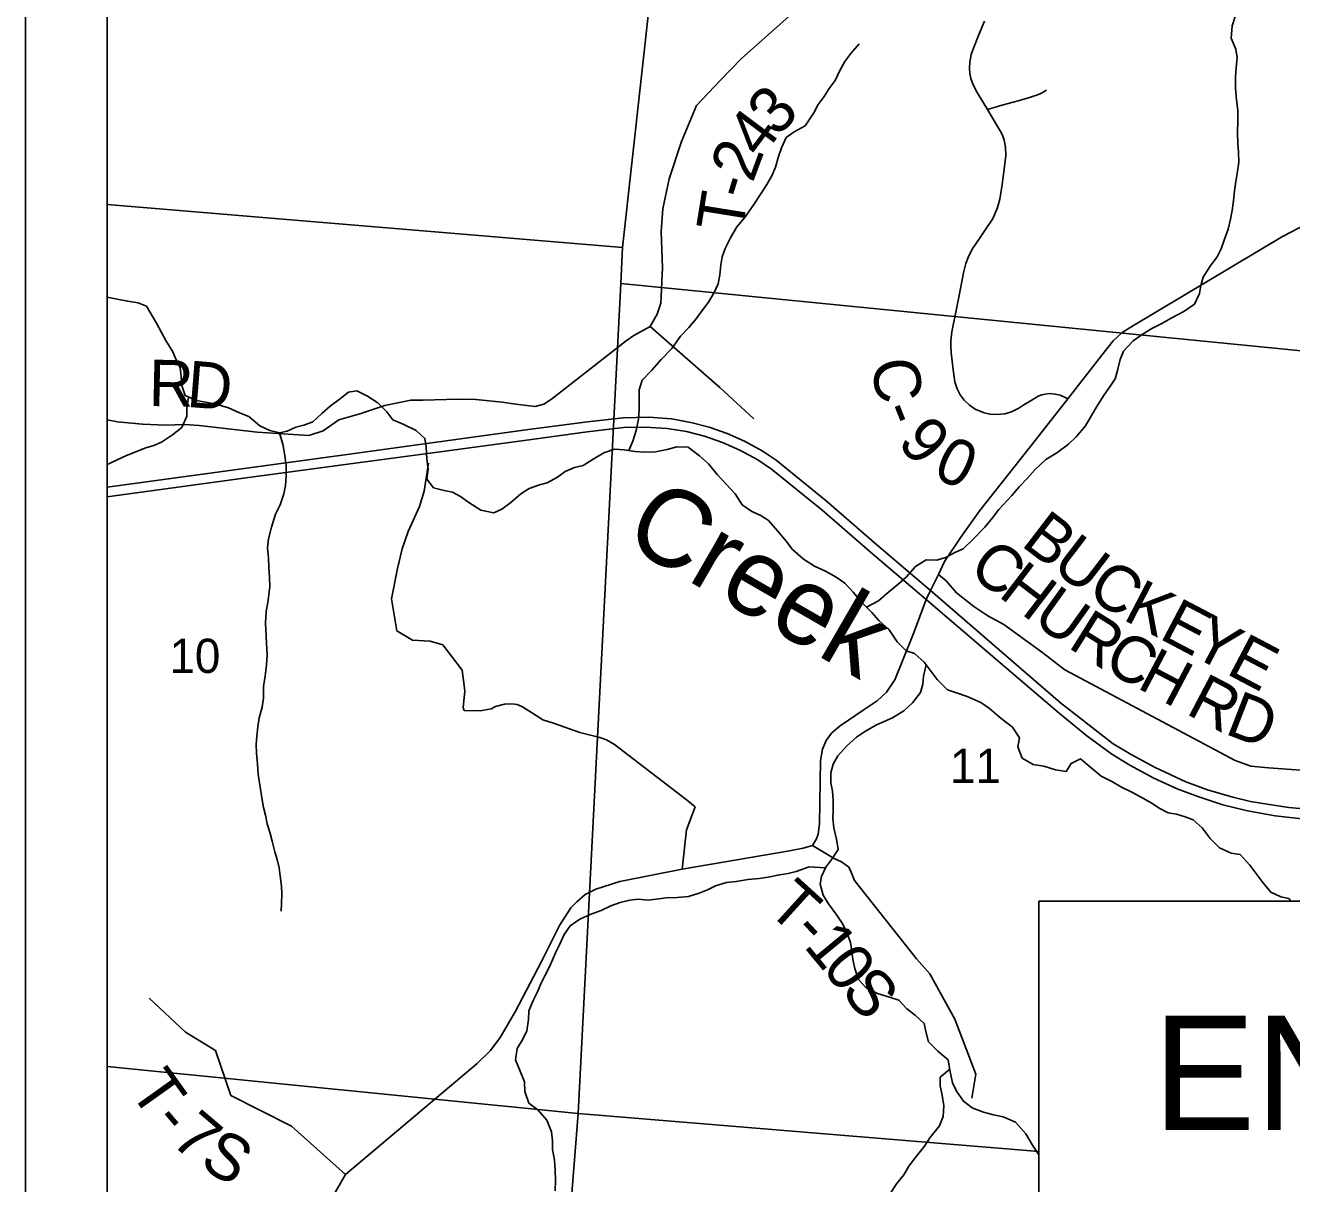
# Model space of a CAD drawing. Extents: x 0 to 34, y 0 to 22.
# Drawn here: x 23.417 to 24.965, y 18.118 to 19.535 of the extents above; entities that cross this region are included whole.
import ezdxf

# ---------------------------------------------------------------- set-up
doc = ezdxf.new("R2010")
doc.units = 0
for name, color, linetype in [('GM_X_Corporation', 7, 'Continuous'), ('GM_X_County_Road', 7, 'Continuous'), ('GM_X_County_Road_Text', 7, 'Continuous'), ('GM_X_Minor_River', 7, 'Continuous'), ('GM_X_Minor_River_Text', 7, 'Continuous'), ('GM_X_Section_Text', 7, 'Continuous'), ('GM_X_State_Route', 7, 'Continuous'), ('GM_X_Township_Road', 7, 'Continuous'), ('GM_X_Township_Road_Text', 7, 'Continuous'), ('SH_Data', 7, 'Continuous'), ('SH_Text', 7, 'Continuous')]:
    doc.layers.add(name, color=color, linetype=linetype)

msp = doc.modelspace()

# ---------------------------------------------------------------- linework, layer by layer
at = {"layer": 'GM_X_Corporation'}
for points in [[(23.5167, 20.1488), (23.5167, 19.3154), (24.147, 19.2629), (24.2381, 20.0885)], [(24.3968, 20.0768), (25.2979, 20.0049), (25.2286, 19.1118), (24.145, 19.219), (24.147, 19.2629), (24.2381, 20.0885)], [(23.5167, 19.3154), (23.5167, 18.2613), (24.0929, 18.2038), (24.145, 19.219), (24.147, 19.2629)], [(23.5167, 18.2613), (23.5167, 17.2158), (24.0111, 17.1749), (24.0929, 18.2038)]]:
    msp.add_lwpolyline(points, close=True, dxfattribs=at)
for points in [[(26.1825, 18.4635), (26.1926, 18.5708), (26.207, 18.8068), (26.2271, 19.0168), (26.2277, 19.0233), (26.2281, 19.0286), (26.3029, 19.931), (25.7174, 19.9778), (25.482, 19.99), (25.2916, 20.0037), (25.117, 20.0172), (24.3889, 20.0736), (24.2296, 20.084), (23.8215, 20.1257), (23.5167, 20.1476), (23.5167, 14.1), (25.8273, 14.1), (25.8671, 14.5774), (25.9626, 15.7291)], [(24.656, 18.1575), (24.0929, 18.2038), (24.145, 19.219), (25.2286, 19.1118), (25.1756, 18.4635)], [(25.0768, 17.6235), (25.0299, 17.0732), (24.0111, 17.1749), (24.0929, 18.2038), (24.656, 18.1575)]]:
    msp.add_lwpolyline(points, dxfattribs=at)
at = {"layer": 'GM_X_County_Road'}
msp.add_lwpolyline([(24.6916, 19.078), (24.6868, 19.0805), (24.6822, 19.0824), (24.6763, 19.0837), (24.6692, 19.0842), (24.664, 19.0836), (24.6597, 19.0826), (24.6554, 19.081), (24.6466, 19.076), (24.6377, 19.0704), (24.6317, 19.0666), (24.6227, 19.0621), (24.6147, 19.0597), (24.6046, 19.0586), (24.5966, 19.0591), (24.5892, 19.0607), (24.5784, 19.0653), (24.5712, 19.0702), (24.5647, 19.0764), (24.56, 19.0828), (24.5562, 19.09), (24.5533, 19.0987), (24.5513, 19.1134), (24.5491, 19.1347), (24.5487, 19.1421), (24.5487, 19.1487), (24.5499, 19.1599), (24.5546, 19.1838), (24.5586, 19.2042), (24.564, 19.232), (24.567, 19.2432), (24.5698, 19.2507), (24.5748, 19.2608), (24.5845, 19.2753), (24.5919, 19.286), (24.5993, 19.2976), (24.602, 19.3029), (24.6057, 19.3118), (24.6086, 19.3219), (24.6114, 19.3401), (24.6142, 19.3622), (24.6158, 19.3755), (24.6154, 19.3856), (24.6136, 19.3944), (24.6115, 19.4003), (24.6089, 19.4057), (24.6041, 19.4138), (24.5932, 19.4319), (24.5876, 19.4411), (24.5806, 19.4526), (24.5758, 19.4618), (24.5731, 19.4696), (24.5719, 19.4759), (24.5713, 19.4824), (24.5716, 19.4898), (24.5734, 19.4989), (24.5761, 19.5068), (24.5824, 19.5222), (24.5895, 19.5398)], dxfattribs=at)
at = {"layer": 'GM_X_Minor_River'}
for points in [[(24.4454, 18.8229), (24.4602, 18.8308), (24.4724, 18.8413), (24.4838, 18.8507), (24.4937, 18.8597), (24.5055, 18.8729), (24.5184, 18.8808), (24.5313, 18.8807), (24.5434, 18.8841), (24.5533, 18.8901), (24.5635, 18.8945), (24.5753, 18.9058), (24.5902, 18.9209), (24.5994, 18.9322), (24.6074, 18.9424), (24.623, 18.9598), (24.6325, 18.9707), (24.6417, 18.9805), (24.6516, 18.9914), (24.6646, 19.0035), (24.6782, 19.0117), (24.6923, 19.0223), (24.7018, 19.0313), (24.7133, 19.0449), (24.7205, 19.0574), (24.7282, 19.0706), (24.7362, 19.0827), (24.7431, 19.0925), (24.7496, 19.1023), (24.7523, 19.1125), (24.7555, 19.1261), (24.7597, 19.136), (24.7715, 19.1488), (24.7825, 19.1567), (24.7943, 19.1638), (24.8065, 19.1698), (24.8178, 19.1766), (24.8334, 19.1848), (24.8467, 19.1938), (24.8525, 19.2067), (24.8544, 19.2165), (24.8572, 19.2267), (24.8656, 19.2403), (24.8744, 19.2517), (24.8793, 19.2615), (24.8828, 19.2721), (24.8875, 19.2853), (24.8906, 19.2978), (24.8925, 19.3084), (24.8941, 19.3202), (24.8953, 19.3323), (24.8969, 19.3437), (24.8985, 19.3535), (24.9009, 19.3672), (24.9002, 19.3797), (24.8995, 19.3896), (24.8989, 19.4032), (24.8993, 19.4184), (24.8994, 19.4309), (24.898, 19.4434), (24.8966, 19.4578), (24.8967, 19.4711), (24.8975, 19.4829), (24.8987, 19.4954), (24.8969, 19.5056), (24.8913, 19.5189), (24.8926, 19.5341), (24.8972, 19.5481)], [(24.1549, 19.0147), (24.1596, 19.0262), (24.1638, 19.039), (24.1665, 19.0531), (24.1674, 19.0648), (24.1675, 19.0887), (24.171, 19.1008), (24.1828, 19.1129), (24.1943, 19.1261), (24.2072, 19.1393), (24.2179, 19.1544), (24.2279, 19.1653), (24.237, 19.1758), (24.2446, 19.1857), (24.2523, 19.1959), (24.2592, 19.2079), (24.2638, 19.2185), (24.2661, 19.2295), (24.2673, 19.2416), (24.2689, 19.2515), (24.2724, 19.2617), (24.2789, 19.2749), (24.2866, 19.2882), (24.2961, 19.2991), (24.3068, 19.3142), (24.3171, 19.3297), (24.3233, 19.3399), (24.3298, 19.3508), (24.334, 19.3614), (24.3379, 19.3743), (24.3414, 19.3849), (24.3471, 19.3974), (24.357, 19.4045), (24.3703, 19.4116), (24.381, 19.4275), (24.3864, 19.4377), (24.3936, 19.4475), (24.3997, 19.4573), (24.407, 19.4671), (24.4128, 19.4796), (24.4189, 19.4906), (24.4261, 19.5004), (24.4364, 19.5121)], [(23.5167, 19.202), (23.5186, 19.2019), (23.5311, 19.1992), (23.542, 19.1972), (23.5545, 19.1952), (23.5647, 19.191), (23.577, 19.1704), (23.5834, 19.159), (23.5883, 19.1491), (23.5969, 19.1354), (23.601, 19.1255), (23.6062, 19.116), (23.6072, 19.1046), (23.6079, 19.094), (23.612, 19.0818), (23.626, 19.076), (23.6415, 19.0729), (23.6513, 19.0709), (23.6653, 19.067), (23.6785, 19.0609), (23.6902, 19.0562), (23.7033, 19.0448), (23.7158, 19.039), (23.7275, 19.0363), (23.737, 19.0385), (23.7476, 19.0433), (23.7574, 19.0456), (23.7681, 19.0497), (23.7791, 19.0598), (23.7894, 19.0689), (23.8023, 19.0782), (23.8118, 19.0861), (23.8221, 19.0876), (23.8353, 19.0811)], [(23.6162, 19.0801), (23.6142, 19.0662), (23.6141, 19.0568), (23.608, 19.0428), (23.5965, 19.0337), (23.5832, 19.0247), (23.5738, 19.0206), (23.5639, 19.018), (23.5525, 19.0135), (23.5396, 19.0083), (23.5297, 19.0038), (23.5203, 18.999), (23.5167, 18.9975)], [(23.8353, 19.0811), (23.8477, 19.073), (23.8586, 19.0619), (23.8661, 19.052), (23.8797, 19.0463), (23.8948, 19.0393), (23.9053, 19.0294), (23.9067, 19.0188), (23.9078, 19.0043), (23.9092, 18.9918), (23.9076, 18.9797), (23.9159, 18.969), (23.9287, 18.9659), (23.9389, 18.9639), (23.9487, 18.9586), (23.9589, 18.9509), (23.9736, 18.9417), (23.9898, 18.9386), (23.9993, 18.9431), (24.0103, 18.9509), (24.0225, 18.9615), (24.0328, 18.9682), (24.0453, 18.9727), (24.0548, 18.9753), (24.0673, 18.982), (24.0768, 18.9888), (24.0882, 18.994), (24.0988, 18.9962), (24.1113, 19.0041), (24.1243, 19.012), (24.1372, 19.0161), (24.1489, 19.0156), (24.1621, 19.0136), (24.1738, 19.0128), (24.1875, 19.0131), (24.2015, 19.0157), (24.2136, 19.019), (24.2272, 19.0189), (24.2412, 19.0082), (24.2521, 18.9983), (24.263, 18.9849), (24.2738, 18.9735), (24.2847, 18.9616), (24.2934, 18.9483), (24.305, 18.9399), (24.3152, 18.9356), (24.325, 18.9295), (24.337, 18.9161), (24.3472, 18.9036), (24.355, 18.8937), (24.3682, 18.8818), (24.3818, 18.8734), (24.3953, 18.8672), (24.4082, 18.8599), (24.4187, 18.8526), (24.4292, 18.8416), (24.4401, 18.8282), (24.4518, 18.8164), (24.4604, 18.8069), (24.4732, 18.7954), (24.4829, 18.7805), (24.4938, 18.7695), (24.504, 18.7664), (24.5161, 18.7557), (24.5232, 18.7461), (24.5318, 18.7347), (24.5446, 18.7221), (24.5555, 18.7182), (24.5684, 18.7136), (24.5853, 18.7063), (24.5959, 18.699), (24.6102, 18.6868), (24.6241, 18.6761), (24.6323, 18.6631), (24.6304, 18.6521), (24.6356, 18.6384), (24.6492, 18.6308), (24.6624, 18.6284), (24.6767, 18.6241), (24.6896, 18.6222), (24.6957, 18.632), (24.7071, 18.6376), (24.7199, 18.6269), (24.7323, 18.6162), (24.7463, 18.6096), (24.7572, 18.6028), (24.77, 18.5966), (24.7798, 18.5916), (24.7934, 18.5836), (24.8039, 18.577), (24.8141, 18.5717), (24.8243, 18.5697), (24.8349, 18.5666), (24.8447, 18.5631), (24.856, 18.5532), (24.8657, 18.5402), (24.877, 18.5288), (24.8913, 18.5222), (24.9023, 18.5206), (24.9143, 18.5077), (24.9226, 18.4959)], [(23.7275, 19.0363), (23.7319, 19.0207), (23.7341, 19.0082), (23.7355, 18.9964), (23.7355, 18.9831), (23.735, 18.9717), (23.733, 18.9615), (23.7284, 18.9483), (23.7227, 18.9369), (23.7176, 18.921), (23.7141, 18.9067), (23.7129, 18.8957), (23.714, 18.8835), (23.7146, 18.8714), (23.7153, 18.8596), (23.7156, 18.8479), (23.7132, 18.8289), (23.7112, 18.8183), (23.7104, 18.8031), (23.711, 18.788), (23.7117, 18.7785), (23.7124, 18.7648), (23.7116, 18.7527), (23.71, 18.7387), (23.708, 18.7262), (23.7079, 18.7117), (23.7063, 18.7008), (23.7028, 18.6879), (23.7012, 18.6765), (23.6996, 18.6652), (23.6988, 18.6553), (23.6995, 18.6447), (23.7005, 18.631), (23.7016, 18.6189), (23.7059, 18.59), (23.7081, 18.5782), (23.7103, 18.5688), (23.7125, 18.5581), (23.7155, 18.5479), (23.7184, 18.5368), (23.7217, 18.5239), (23.7247, 18.5144), (23.7269, 18.5042), (23.7283, 18.4943), (23.7298, 18.4818), (23.7305, 18.4719), (23.73, 18.4605), (23.7296, 18.4511)], [(24.5184, 18.7526), (24.5152, 18.7386), (24.5144, 18.7288), (24.5113, 18.7185), (24.5017, 18.7061), (24.4911, 18.6963), (24.477, 18.6877), (24.4671, 18.6832), (24.4576, 18.6791), (24.4443, 18.6716), (24.4333, 18.6641), (24.4208, 18.6531), (24.4105, 18.6414), (24.4047, 18.6309), (24.4016, 18.6206), (24.4019, 18.6081), (24.4037, 18.5979), (24.4048, 18.5869), (24.4047, 18.574), (24.4043, 18.5645), (24.4053, 18.5531), (24.4086, 18.5394), (24.4108, 18.5265), (24.4028, 18.5148), (24.3955, 18.505), (24.3902, 18.4937), (24.3886, 18.4842), (24.3923, 18.4709), (24.399, 18.4602), (24.4091, 18.4465), (24.4155, 18.4366), (24.4207, 18.4271), (24.4259, 18.413), (24.4274, 18.4024), (24.4288, 18.3922), (24.431, 18.3811), (24.4355, 18.3678), (24.4445, 18.3579), (24.4588, 18.3506), (24.4735, 18.346), (24.4849, 18.3425), (24.4946, 18.3318), (24.5048, 18.3241), (24.5161, 18.3138), (24.5179, 18.304), (24.5212, 18.2914), (24.5325, 18.28), (24.5453, 18.2693), (24.5471, 18.2567), (24.5504, 18.2415), (24.5556, 18.2313), (24.5639, 18.2187), (24.5748, 18.2107), (24.5884, 18.2053), (24.6008, 18.2021), (24.6125, 18.1998), (24.6276, 18.1932), (24.6404, 18.1791), (24.6483, 18.165), (24.656, 18.1531)], [(24.3951, 18.5041), (24.3751, 18.5055), (24.3592, 18.4999), (24.3497, 18.4974), (24.3391, 18.4955), (24.3251, 18.493), (24.3141, 18.4911), (24.3005, 18.4901), (24.2861, 18.4875), (24.2743, 18.4865), (24.2607, 18.4824), (24.2508, 18.4775), (24.2409, 18.4734), (24.2277, 18.4693), (24.214, 18.4679), (24.2008, 18.4676), (24.1883, 18.4658), (24.1784, 18.4647), (24.1663, 18.466), (24.1561, 18.4649), (24.144, 18.4619), (24.1326, 18.4578), (24.1208, 18.4522), (24.1076, 18.447), (24.095, 18.4414), (24.0829, 18.4335), (24.0756, 18.4229), (24.0698, 18.4101), (24.0652, 18.4003), (24.0575, 18.3832), (24.0522, 18.373), (24.0472, 18.3625), (24.043, 18.3526), (24.038, 18.3428), (24.0326, 18.3292), (24.0321, 18.3186), (24.0298, 18.3049), (24.0252, 18.2947), (24.0183, 18.2834), (24.0163, 18.2694), (24.0219, 18.2557), (24.0271, 18.2427), (24.0274, 18.2306), (24.0326, 18.2165), (24.0435, 18.2081), (24.0544, 18.1955), (24.0603, 18.1815), (24.0614, 18.1705), (24.0613, 18.1598), (24.0639, 18.1469), (24.0646, 18.1344), (24.0652, 18.1223), (24.0648, 18.1094)], [(24.9226, 18.4959), (24.9301, 18.4863), (24.9398, 18.4745), (24.9519, 18.4687), (24.9617, 18.4668), (24.9642, 18.4635)], [(24.547, 18.2577), (24.5353, 18.2481), (24.5356, 18.2375), (24.5378, 18.2261), (24.54, 18.2132), (24.5391, 18.2003), (24.5345, 18.1889), (24.5227, 18.1742), (24.5162, 18.164), (24.5047, 18.1497), (24.4971, 18.1395), (24.491, 18.1289), (24.4822, 18.1176), (24.4734, 18.1044), (24.4684, 18.0919), (24.4645, 18.0794), (24.458, 18.0688), (24.4496, 18.0567), (24.4412, 18.0466), (24.4381, 18.0367), (24.4346, 18.025), (24.4327, 18.0117), (24.4326, 17.9984), (24.4318, 17.983)]]:
    msp.add_lwpolyline(points, dxfattribs=at)
at = {"layer": 'GM_X_State_Route'}
for points in [[(24.5182, 18.8324), (24.5236, 18.8435), (24.5333, 18.8632), (24.5409, 18.879), (24.5606, 18.9088), (24.584, 18.9412), (24.6517, 19.027), (24.6916, 19.078), (24.7333, 19.1311), (24.7471, 19.1486), (24.7582, 19.1588), (24.772, 19.1675), (24.954, 19.2762), (24.9839, 19.2919)], [(23.5167, 18.9698), (23.6544, 18.9884), (23.8132, 19.0101), (23.9196, 19.0247), (24.0321, 19.0402), (24.104, 19.0499), (24.1479, 19.0545), (24.179, 19.0553), (24.2068, 19.0532), (24.2307, 19.0489), (24.2528, 19.0431), (24.2748, 19.0355), (24.296, 19.0262), (24.3179, 19.0142), (24.3347, 19.0028), (24.3961, 18.953), (24.4581, 18.8993), (24.5236, 18.8435), (24.6828, 18.7062), (24.7472, 18.6561), (24.7691, 18.6427), (24.7984, 18.6268), (24.8361, 18.6094), (24.8624, 18.5995), (24.8935, 18.5908), (24.9151, 18.5855), (24.9379, 18.5816), (24.9619, 18.578), (24.9891, 18.5758)], [(23.5167, 18.9582), (23.6959, 18.9823), (23.82, 18.999), (23.9116, 19.0114), (24.0269, 19.0268), (24.1039, 19.0375), (24.148, 19.0429), (24.1748, 19.0434), (24.2014, 19.0414), (24.2253, 19.0378), (24.2473, 19.032), (24.2694, 19.0245), (24.2906, 19.0151), (24.3125, 19.0031), (24.3293, 18.9917), (24.3906, 18.9419), (24.4526, 18.8883), (24.5182, 18.8324)], [(24.4086, 18.6742), (24.4132, 18.678), (24.4424, 18.6981), (24.4586, 18.7083), (24.4697, 18.719), (24.4799, 18.7343), (24.4893, 18.7574), (24.503, 18.7907), (24.5182, 18.8324)], [(24.5182, 18.8324), (24.5974, 18.7646), (24.6811, 18.6934), (24.7147, 18.6656), (24.7456, 18.6432), (24.7675, 18.6299), (24.7968, 18.6139), (24.8254, 18.6009), (24.8504, 18.5914), (24.8813, 18.5815), (24.9113, 18.5741), (24.945, 18.568), (24.9739, 18.5647), (25.0076, 18.5634), (25.0428, 18.5638), (25.0725, 18.5666), (25.0952, 18.5702), (25.1205, 18.5754), (25.1245, 18.5764), (25.1479, 18.5819)], [(23.7608, 18.0471), (23.8083, 18.1293), (23.9691, 18.265), (23.9856, 18.2808), (23.9972, 18.2966), (24.0157, 18.3281), (24.0479, 18.3896), (24.0701, 18.4339), (24.0838, 18.4553), (24.091, 18.4625), (24.1015, 18.4718), (24.1144, 18.4782), (24.1438, 18.4875), (24.2198, 18.5025), (24.3512, 18.5252), (24.3679, 18.5284), (24.3792, 18.5317), (24.3844, 18.5399), (24.3863, 18.5454), (24.3878, 18.5582), (24.3891, 18.6355), (24.3914, 18.6492), (24.3961, 18.6598), (24.4026, 18.6691), (24.4086, 18.6742)]]:
    msp.add_lwpolyline(points, dxfattribs=at)
at = {"layer": 'GM_X_Township_Road'}
for points in [[(24.1809, 19.1665), (24.1894, 19.1814), (24.1937, 19.1947), (24.1958, 19.2382), (24.1944, 19.2827), (24.1965, 19.3102), (24.2041, 19.3469), (24.2193, 19.3925), (24.2375, 19.4365), (24.267, 19.4677), (24.2924, 19.4939), (24.4633, 19.6463), (24.5313, 19.7046), (24.546, 19.7172)], [(24.5932, 19.4319), (24.6124, 19.4373), (24.6308, 19.4425), (24.6447, 19.4465), (24.6533, 19.4491), (24.6577, 19.4509), (24.6657, 19.4555)], [(23.5167, 19.0521), (23.5293, 19.0499), (23.5601, 19.0467), (23.5875, 19.0456), (23.6114, 19.0464), (23.6292, 19.0453), (23.7, 19.0372), (23.7633, 19.0332), (23.7811, 19.0389), (23.8001, 19.0522), (23.8284, 19.0603), (23.8295, 19.0608), (23.8562, 19.0697), (23.8882, 19.0761), (23.9032, 19.0761), (23.945, 19.0773), (23.9676, 19.0769), (24, 19.0739), (24.0166, 19.0714), (24.0401, 19.0684), (24.0508, 19.0714), (24.0601, 19.0773), (24.1514, 19.1486), (24.1608, 19.1554), (24.1809, 19.1665), (24.1975, 19.1516), (24.2662, 19.0918), (24.3076, 19.0534)], [(24.2198, 18.5025), (24.2254, 18.5508), (24.232, 18.5691), (24.2358, 18.5788), (24.2247, 18.5878), (24.1721, 18.6283), (24.137, 18.6551), (24.1274, 18.6608), (24.1191, 18.6636), (24.0946, 18.6698), (24.0626, 18.681), (24.0497, 18.6852), (24.0415, 18.6906), (24.0245, 18.7013), (24.0182, 18.7041), (24.0115, 18.705), (24.0027, 18.7044), (23.9918, 18.7015), (23.9865, 18.6986), (23.9728, 18.6964), (23.9532, 18.6968), (23.952, 18.7001), (23.954, 18.7209), (23.9507, 18.7459), (23.9272, 18.777), (23.9117, 18.7816), (23.8901, 18.7828), (23.8712, 18.7943), (23.8645, 18.8331), (23.8719, 18.8702), (23.8777, 18.8945), (23.885, 18.9154), (23.8988, 18.946), (23.9045, 18.965), (23.9098, 18.9991)], [(24.5333, 18.8632), (24.5426, 18.8551), (24.5554, 18.8406), (24.5768, 18.8239), (24.5938, 18.8124), (24.6135, 18.8018), (24.6612, 18.7672), (24.6881, 18.7463), (24.8963, 18.6356), (24.9152, 18.6286), (24.9369, 18.6265), (25.146, 18.6116)], [(24.3792, 18.5317), (24.4058, 18.5156), (24.4146, 18.5114), (24.4232, 18.5055), (24.4258, 18.501), (24.4308, 18.4887), (24.5067, 18.393), (24.5227, 18.3747), (24.5535, 18.3192), (24.5789, 18.252), (24.5741, 18.2226)], [(23.8083, 18.1293), (23.7423, 18.1881), (23.6681, 18.226), (23.6494, 18.2809), (23.6126, 18.3031), (23.5682, 18.3449)]]:
    msp.add_lwpolyline(points, dxfattribs=at)
at = {"layer": 'SH_Data'}
for points in [[(23.4167, 21), (30.4167, 21), (30.4167, 14), (23.4167, 14)], [(23.5167, 20.9), (30.3167, 20.9), (30.3167, 14.1), (23.5167, 14.1)], [(24.656, 18.4635), (26.3421, 18.4635), (26.3421, 17.6235), (24.656, 17.6235)]]:
    msp.add_lwpolyline(points, close=True, dxfattribs=at)

# ---------------------------------------------------------------- texts
at = {"layer": 'GM_X_County_Road_Text'}
for s, rotation, p in [('C', 278.1085, (24.4511, 19.124)), ('-', 291.4996, (24.4613, 19.0642)), ('9', 312.3492, (24.4816, 19.0236)), ('0', 334.7184, (24.5244, 18.9836))]:
    msp.add_text(s, height=0.0568, rotation=rotation, dxfattribs=at).set_placement(p)
at = {"layer": 'GM_X_Minor_River_Text'}
msp.add_text('Creek', height=0.0947, rotation=329.9966, dxfattribs=at).set_placement((24.1451, 18.9026))
at = {"layer": 'GM_X_Section_Text'}
for s, p in [('10', (23.5929, 18.7426)), ('11', (24.5475, 18.608))]:
    msp.add_text(s, height=0.04186, rotation=0, dxfattribs=at).set_placement(p)
at = {"layer": 'GM_X_Township_Road_Text'}
for s, rotation, p in [('3', 46.5273, (24.336, 19.3968)), ('4', 53.2602, (24.3162, 19.3701)), ('2', 69.687, (24.3061, 19.341)), ('-', 72.8783, (24.2994, 19.3195)), ('T', 80.8632, (24.2932, 19.2796)), ('R', 358.8993, (23.5672, 19.0691)), ('D', 355.3943, (23.6129, 19.0682)), ('B', 322.5478, (24.6329, 18.8992)), ('U', 322.5458, (24.6699, 18.8708)), ('C', 322.6063, (24.5679, 18.8655)), ('H', 322.6965, (24.6051, 18.8371)), ('C', 325.9994, (24.7127, 18.8382)), ('U', 324.4333, (24.6463, 18.8057)), ('K', 332.5557, (24.7574, 18.8085)), ('E', 332.2409, (24.8017, 18.7855)), ('R', 327.914, (24.6901, 18.7745)), ('Y', 332.2408, (24.8394, 18.7657)), ('C', 331.2523, (24.7328, 18.7479)), ('E', 332.2409, (24.8836, 18.7424)), ('H', 332.1546, (24.7746, 18.725)), ('R', 332.2926, (24.8344, 18.6934)), ('D', 338.7941, (24.8821, 18.6688)), ('T', 317.792, (24.3217, 18.4524)), ('-', 313.1175, (24.3523, 18.4247)), ('1', 309.5571, (24.3676, 18.4084)), ('0', 308.6281, (24.3898, 18.3816)), ('S', 310.2024, (24.4127, 18.3529)), ('T', 305.472, (23.5429, 18.2318)), ('-', 310.193, (23.5707, 18.1932)), ('7', 319.6351, (23.5929, 18.1681)), ('S', 329.0772, (23.6279, 18.1395))]:
    msp.add_text(s, height=0.0568, rotation=rotation, dxfattribs=at).set_placement(p)
at = {"layer": 'SH_Text'}
msp.add_text('END PROJECT', height=0.14, dxfattribs=at).set_placement((24.796, 18.1835))

doc.saveas('drawing.dxf')
